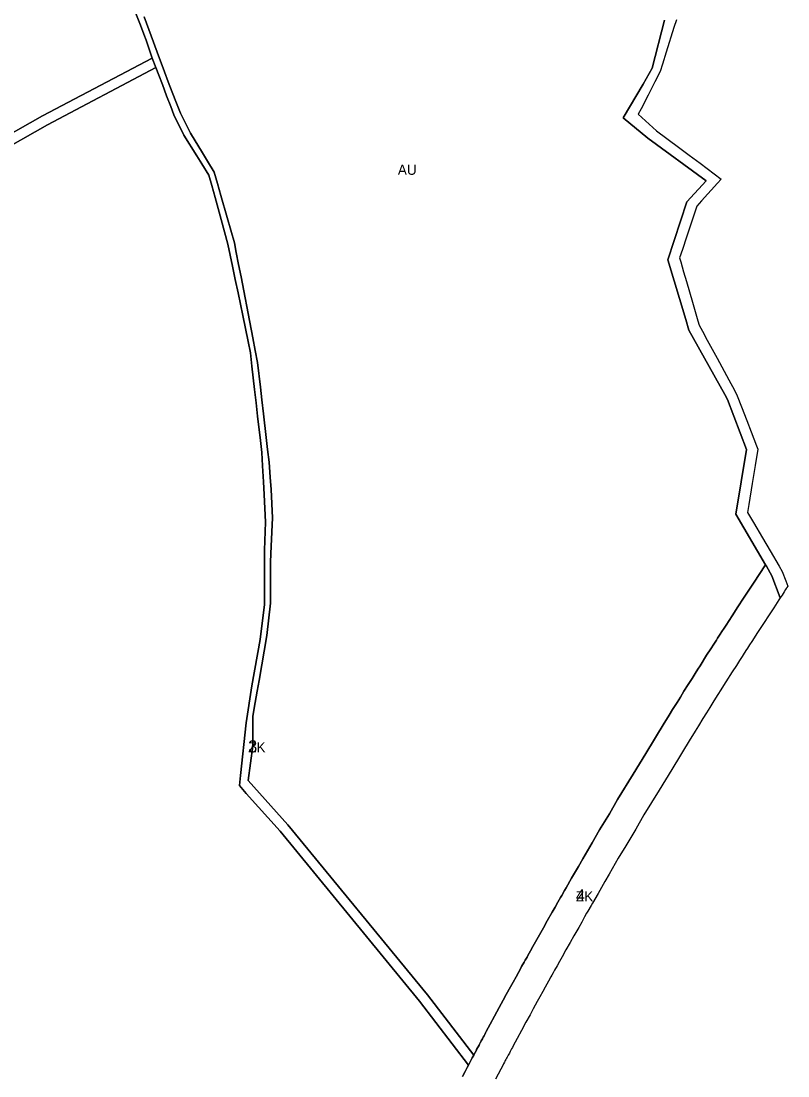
# Model space of a CAD drawing. Extents: x -537068 to -534056, y -1176840 to -1172401.
# Drawn here: x -536126 to -535749, y -1173679 to -1173160 of the extents above; entities that cross this region are included whole.
import ezdxf

# ---------------------------------------------------------------- set-up
doc = ezdxf.new("R2010")
doc.units = 0
for name, color, linetype in [('90710023', 7, 'Continuous'), ('90750013', 7, 'Continuous'), ('ID_navrh', 7, 'Continuous')]:
    doc.layers.add(name, color=color, linetype=linetype)

msp = doc.modelspace()

# ---------------------------------------------------------------- linework, layer by layer
at = {"layer": '90710023'}
for points in [[(-536065.55, -1173157.97), (-536062.1, -1173167.32), (-536059.13, -1173175.37), (-536055.51, -1173185.16), (-536053.65, -1173189.98), (-536051.66, -1173195.15), (-536049.6, -1173200.51), (-536047.69, -1173205.46), (-536042.77, -1173215.28), (-536036.86, -1173224.98), (-536034.34, -1173229.1), (-536031.04, -1173234.52), (-536029.45, -1173240.07), (-536027.76, -1173245.96), (-536024.67, -1173256.74), (-536021.09, -1173269.25), (-536020.15, -1173273.99), (-536018.99, -1173279.85), (-536017.77, -1173286), (-536016.39, -1173292.96), (-536014.27, -1173304.03), (-536011.97, -1173316.03), (-536010.78, -1173322.21), (-536009.63, -1173328.22), (-536008.28, -1173340.22), (-536007.57, -1173346.57), (-536006.8, -1173353.38), (-536005.48, -1173365.05), (-536004.73, -1173370.93), (-536003.93, -1173377.2), (-536003.43, -1173384.66), (-536003.02, -1173390.65), (-536002.3, -1173404.63), (-536002.99, -1173418.53), (-536003.38, -1173426.31), (-536003.35, -1173433.33), (-536003.3, -1173446.59), (-536005.11, -1173462.48), (-536008.94, -1173484.69), (-536009.84, -1173489.93), (-536010.81, -1173495.52), (-536011.97, -1173502.26), (-536012.07, -1173516.8), (-536014.28, -1173533.95), (-535994.71, -1173555.65), (-535926, -1173639.4), (-535903.28, -1173669.08), (-535904.02, -1173670.46), (-535905.86, -1173673.94), (-535929.92, -1173642.51), (-535998.5, -1173558.91), (-536015.29, -1173540.29), (-536018.62, -1173536.28), (-536018.08, -1173531.45), (-536015.31, -1173505.45), (-536012.55, -1173487.33), (-536008.37, -1173464.48), (-536006.32, -1173447.22), (-536006.32, -1173434.45), (-536006.31, -1173420.53), (-536005.72, -1173406.73), (-536006.38, -1173393.17), (-536006.76, -1173386.89), (-536007.24, -1173378.98), (-536007.64, -1173372.39), (-536008.3, -1173366.53), (-536009.65, -1173354.61), (-536010.39, -1173348.05), (-536011.14, -1173341.39), (-536012.43, -1173330.02), (-536013.18, -1173323.35), (-536014.34, -1173317.77), (-536016.98, -1173305.06), (-536019.31, -1173293.84), (-536020.65, -1173287.38), (-536022.03, -1173280.77), (-536023.15, -1173275.37), (-536024.29, -1173269.88), (-536027.6, -1173257.84), (-536030.57, -1173247.02), (-536032.22, -1173240.99), (-536033.6, -1173235.97), (-536037.11, -1173230.34), (-536039.56, -1173226.42), (-536045.93, -1173216.22), (-536050.86, -1173206.32), (-536052.44, -1173202.14), (-536054.44, -1173196.88), (-536056.52, -1173191.4), (-536058.32, -1173186.65), (-536059.71, -1173182.99), (-536061.49, -1173178.28), (-536064.6, -1173169.52), (-536065.68, -1173166.48), (-536067.25, -1173162.07), (-536069.87, -1173155.47)], [(-535803.45, -1173159.52), (-535804.66, -1173163.34), (-535808.48, -1173175.4), (-535810.33, -1173181.24), (-535811.49, -1173184.9), (-535814.13, -1173190.06), (-535817.43, -1173196.52), (-535820.87, -1173203.25), (-535822.27, -1173205.99), (-535813.3, -1173214.08), (-535802.36, -1173222.24), (-535797.19, -1173226.1), (-535791.83, -1173230.1), (-535781.43, -1173237.85), (-535783.31, -1173239.94), (-535791.08, -1173248.57), (-535793.43, -1173251.18), (-535794.57, -1173254.61), (-535798.54, -1173266.53), (-535800.51, -1173272.46), (-535801.9, -1173276.62), (-535801.34, -1173278.55), (-535799.91, -1173283.48), (-535798.52, -1173288.28), (-535795.57, -1173298.46), (-535792.93, -1173307.6), (-535792.31, -1173309.75), (-535790.69, -1173312.73), (-535788.33, -1173317.08), (-535783.48, -1173326.02), (-535777.69, -1173336.69), (-535774.9, -1173341.83), (-535773.51, -1173344.62), (-535771.43, -1173350.02), (-535768.86, -1173356.67), (-535766.68, -1173362.33), (-535764.02, -1173369.25), (-535763.42, -1173370.8), (-535764.71, -1173378.86), (-535766.14, -1173387.77), (-535767.79, -1173398.05), (-535768.43, -1173402.02), (-535765.58, -1173406.86), (-535761.14, -1173414.39), (-535757.31, -1173420.88), (-535752.87, -1173428.42), (-535751.35, -1173430.99), (-535749.58, -1173435.6), (-535748.57, -1173438.22), (-535749.05, -1173438.92), (-535749.18, -1173439.12), (-535749.4, -1173439.46), (-535749.69, -1173439.9), (-535750.38, -1173440.96), (-535751.46, -1173442.6), (-535752.34, -1173443.92), (-535756.52, -1173433.09), (-535759.12, -1173428.42), (-535759.55, -1173427.69), (-535774.26, -1173402.73), (-535768.96, -1173371.03), (-535778.38, -1173346.41), (-535779.58, -1173343.92), (-535797.43, -1173312.23), (-535798.87, -1173306.98), (-535807.63, -1173277.69), (-535798.31, -1173249.15), (-535788.85, -1173238.8), (-535817.5, -1173217.68), (-535829.73, -1173207.78), (-535819.85, -1173191.11), (-535815.41, -1173183.23), (-535809.4, -1173159.72)], [(-536141.23, -1173221.22), (-536115.5, -1173206.7), (-536061.49, -1173178.28), (-536059.71, -1173182.99), (-536113.11, -1173211.09), (-536138.71, -1173225.54)], [(-535908.86, -1173679.62), (-535907.55, -1173677.14), (-535906.46, -1173675.09), (-535905.86, -1173673.94), (-535904.02, -1173670.46), (-535903.28, -1173669.08), (-535903.17, -1173668.87), (-535901.95, -1173666.59), (-535901.85, -1173666.38), (-535900.65, -1173664.14), (-535900.43, -1173663.74), (-535900.25, -1173663.39), (-535900.07, -1173663.07), (-535899.92, -1173662.79), (-535899.7, -1173662.38), (-535899.55, -1173662.09), (-535898.96, -1173660.98), (-535898.55, -1173660.22), (-535898.18, -1173659.52), (-535897.82, -1173658.85), (-535897.4, -1173658.09), (-535897.06, -1173657.45), (-535895.11, -1173653.88), (-535893.03, -1173649.85), (-535890.69, -1173645.55), (-535888.68, -1173642), (-535887.23, -1173639.23), (-535885.13, -1173635.47), (-535883.83, -1173633.11), (-535882.43, -1173630.59), (-535881.19, -1173628.33), (-535880.38, -1173626.87), (-535879.66, -1173625.53), (-535878.39, -1173623.27), (-535877.92, -1173622.41), (-535877.28, -1173621.27), (-535877.01, -1173620.8), (-535876.65, -1173620.11), (-535875.3, -1173617.76), (-535874.16, -1173615.65), (-535872.87, -1173613.38), (-535870.94, -1173609.84), (-535868.92, -1173606.35), (-535867.06, -1173602.94), (-535864.58, -1173598.72), (-535863.19, -1173596.23), (-535861.81, -1173593.77), (-535860.6, -1173591.56), (-535859.92, -1173590.48), (-535858.52, -1173588.01), (-535857.79, -1173586.75), (-535855.05, -1173582), (-535851.73, -1173576.17), (-535849.58, -1173572.47), (-535845.01, -1173564.51), (-535841.25, -1173558.24), (-535836.45, -1173550.32), (-535832.4, -1173543.21), (-535824.81, -1173530.76), (-535818.58, -1173520.62), (-535809.53, -1173505.74), (-535808.34, -1173503.8), (-535807.01, -1173501.67), (-535805.35, -1173498.96), (-535803.13, -1173495.5), (-535801.49, -1173492.81), (-535799.75, -1173489.97), (-535797.64, -1173486.68), (-535795.75, -1173483.65), (-535794.22, -1173481.21), (-535792.89, -1173479.13), (-535791.81, -1173477.39), (-535788.58, -1173472.27), (-535786.52, -1173469.1), (-535785.09, -1173466.85), (-535783.78, -1173464.76), (-535783.18, -1173463.84), (-535781.92, -1173461.89), (-535781.08, -1173460.57), (-535780, -1173458.96), (-535779.02, -1173457.4), (-535776.09, -1173452.86), (-535773.22, -1173448.37), (-535770.39, -1173444.13), (-535768.15, -1173440.65), (-535765.55, -1173436.7), (-535759.55, -1173427.69), (-535759.12, -1173428.42), (-535756.52, -1173433.09), (-535752.34, -1173443.92), (-535753.05, -1173444.98), (-535755.58, -1173448.83), (-535757.85, -1173452.35), (-535760.66, -1173456.57), (-535763.47, -1173460.97), (-535766.37, -1173465.46), (-535767.41, -1173467.11), (-535768.51, -1173468.76), (-535769.29, -1173469.99), (-535770.58, -1173471.97), (-535771.12, -1173472.81), (-535772.4, -1173474.86), (-535773.9, -1173477.22), (-535775.95, -1173480.36), (-535779.1, -1173485.35), (-535780.2, -1173487.12), (-535781.54, -1173489.23), (-535783.04, -1173491.61), (-535784.97, -1173494.7), (-535787.04, -1173497.94), (-535788.7, -1173500.63), (-535790.41, -1173503.44), (-535792.64, -1173506.93), (-535794.26, -1173509.57), (-535795.59, -1173511.7), (-535796.72, -1173513.55), (-535805.78, -1173528.45), (-535812.02, -1173538.6), (-535819.48, -1173550.82), (-535823.51, -1173557.91), (-535828.4, -1173565.98), (-535832.07, -1173572.1), (-535836.59, -1173579.98), (-535838.73, -1173583.65), (-535842.03, -1173589.46), (-535844.79, -1173594.23), (-535845.5, -1173595.47), (-535847.04, -1173598.17), (-535847.65, -1173599.15), (-535848.69, -1173601.04), (-535850.1, -1173603.55), (-535851.56, -1173606.18), (-535854.01, -1173610.34), (-535855.84, -1173613.7), (-535857.86, -1173617.18), (-535859.76, -1173620.67), (-535861.04, -1173622.93), (-535862.2, -1173625.07), (-535863.5, -1173627.33), (-535863.82, -1173627.94), (-535864.19, -1173628.6), (-535864.82, -1173629.72), (-535865.29, -1173630.57), (-535866.5, -1173632.73), (-535867.21, -1173634.07), (-535868.07, -1173635.6), (-535869.29, -1173637.83), (-535870.7, -1173640.37), (-535872.01, -1173642.75), (-535874.03, -1173646.36), (-535875.5, -1173649.17), (-535877.58, -1173652.84), (-535879.78, -1173656.88), (-535881.86, -1173660.91), (-535883.86, -1173664.58), (-535884.21, -1173665.24), (-535884.64, -1173666.01), (-535884.96, -1173666.61), (-535885.31, -1173667.27), (-535885.72, -1173668.05), (-535886.31, -1173669.14), (-535886.46, -1173669.43), (-535886.68, -1173669.83), (-535886.84, -1173670.13), (-535887.04, -1173670.5), (-535887.21, -1173670.83), (-535887.43, -1173671.24), (-535887.71, -1173671.75), (-535887.91, -1173672.13), (-535888.16, -1173672.6), (-535888.55, -1173673.33), (-535888.56, -1173673.34), (-535888.56, -1173673.35), (-535888.57, -1173673.37), (-535888.58, -1173673.38), (-535888.58, -1173673.39), (-535888.58, -1173673.4), (-535888.59, -1173673.4), (-535888.59, -1173673.41), (-535888.6, -1173673.43), (-535888.61, -1173673.44), (-535888.62, -1173673.46), (-535889.92, -1173675.92), (-535891.24, -1173678.38), (-535892.54, -1173680.85)]]:
    msp.add_lwpolyline(points, dxfattribs=at)
at = {"layer": '90750013'}
for points in [[(-536069.87, -1173155.47), (-536067.25, -1173162.07), (-536065.68, -1173166.48), (-536064.6, -1173169.52), (-536061.49, -1173178.28), (-536115.5, -1173206.7), (-536141.23, -1173221.22)], [(-535809.4, -1173159.72), (-535815.41, -1173183.23), (-535819.85, -1173191.11), (-535829.73, -1173207.78), (-535817.5, -1173217.68), (-535788.85, -1173238.8), (-535798.31, -1173249.15), (-535807.63, -1173277.69), (-535798.87, -1173306.98), (-535797.43, -1173312.23), (-535779.58, -1173343.92), (-535778.38, -1173346.41), (-535768.96, -1173371.03), (-535774.26, -1173402.73), (-535759.55, -1173427.69), (-535765.55, -1173436.7), (-535768.15, -1173440.65), (-535770.39, -1173444.13), (-535773.22, -1173448.37), (-535776.09, -1173452.86), (-535779.02, -1173457.4), (-535780, -1173458.96), (-535781.08, -1173460.57), (-535781.92, -1173461.89), (-535783.18, -1173463.84), (-535783.78, -1173464.76), (-535785.09, -1173466.85), (-535786.52, -1173469.1), (-535788.58, -1173472.27), (-535791.81, -1173477.39), (-535792.89, -1173479.13), (-535794.22, -1173481.21), (-535795.75, -1173483.65), (-535797.64, -1173486.68), (-535799.75, -1173489.97), (-535801.49, -1173492.81), (-535803.13, -1173495.5), (-535805.35, -1173498.96), (-535807.01, -1173501.67), (-535808.34, -1173503.8), (-535809.53, -1173505.74), (-535818.58, -1173520.62), (-535824.81, -1173530.76), (-535832.4, -1173543.21), (-535836.45, -1173550.32), (-535841.25, -1173558.24), (-535845.01, -1173564.51), (-535849.58, -1173572.47), (-535851.73, -1173576.17), (-535855.05, -1173582), (-535857.79, -1173586.75), (-535858.52, -1173588.01), (-535859.92, -1173590.48), (-535860.6, -1173591.56), (-535861.81, -1173593.77), (-535863.19, -1173596.23), (-535864.58, -1173598.72), (-535867.06, -1173602.94), (-535868.92, -1173606.35), (-535870.94, -1173609.84), (-535872.87, -1173613.38), (-535874.16, -1173615.65), (-535875.3, -1173617.76), (-535876.65, -1173620.11), (-535877.01, -1173620.8), (-535877.28, -1173621.27), (-535877.92, -1173622.41), (-535878.39, -1173623.27), (-535879.66, -1173625.53), (-535880.38, -1173626.87), (-535881.19, -1173628.33), (-535882.43, -1173630.59), (-535883.83, -1173633.11), (-535885.13, -1173635.47), (-535887.23, -1173639.23), (-535888.68, -1173642), (-535890.69, -1173645.55), (-535893.03, -1173649.85), (-535895.11, -1173653.88), (-535897.06, -1173657.45), (-535897.4, -1173658.09), (-535897.82, -1173658.85), (-535898.18, -1173659.52), (-535898.55, -1173660.22), (-535898.96, -1173660.98), (-535899.55, -1173662.09), (-535899.7, -1173662.38), (-535899.92, -1173662.79), (-535900.07, -1173663.07), (-535900.25, -1173663.39), (-535900.43, -1173663.74), (-535900.65, -1173664.14), (-535901.85, -1173666.38), (-535901.95, -1173666.59), (-535903.17, -1173668.87), (-535903.28, -1173669.08), (-535926, -1173639.4), (-535994.71, -1173555.65), (-536014.28, -1173533.95), (-536012.07, -1173516.8), (-536011.97, -1173502.26), (-536010.81, -1173495.52), (-536009.84, -1173489.93), (-536008.94, -1173484.69), (-536005.11, -1173462.48), (-536003.3, -1173446.59), (-536003.35, -1173433.33), (-536003.38, -1173426.31), (-536002.99, -1173418.53), (-536002.3, -1173404.63), (-536003.02, -1173390.65), (-536003.43, -1173384.66), (-536003.93, -1173377.2), (-536004.73, -1173370.93), (-536005.48, -1173365.05), (-536006.8, -1173353.38), (-536007.57, -1173346.57), (-536008.28, -1173340.22), (-536009.63, -1173328.22), (-536010.78, -1173322.21), (-536011.97, -1173316.03), (-536014.27, -1173304.03), (-536016.39, -1173292.96), (-536017.77, -1173286), (-536018.99, -1173279.85), (-536020.15, -1173273.99), (-536021.09, -1173269.25), (-536024.67, -1173256.74), (-536027.76, -1173245.96), (-536029.45, -1173240.07), (-536031.04, -1173234.52), (-536034.34, -1173229.1), (-536036.86, -1173224.98), (-536042.77, -1173215.28), (-536047.69, -1173205.46), (-536049.6, -1173200.51), (-536051.66, -1173195.15), (-536053.65, -1173189.98), (-536055.51, -1173185.16), (-536059.13, -1173175.37), (-536062.1, -1173167.32), (-536065.55, -1173157.97)], [(-536138.71, -1173225.54), (-536113.11, -1173211.09), (-536059.71, -1173182.99), (-536058.32, -1173186.65), (-536056.52, -1173191.4), (-536054.44, -1173196.88), (-536052.44, -1173202.14), (-536050.86, -1173206.32), (-536045.93, -1173216.22), (-536039.56, -1173226.42), (-536037.11, -1173230.34), (-536033.6, -1173235.97), (-536032.22, -1173240.99), (-536030.57, -1173247.02), (-536027.6, -1173257.84), (-536024.29, -1173269.88), (-536023.15, -1173275.37), (-536022.03, -1173280.77), (-536020.65, -1173287.38), (-536019.31, -1173293.84), (-536016.98, -1173305.06), (-536014.34, -1173317.77), (-536013.18, -1173323.35), (-536012.43, -1173330.02), (-536011.14, -1173341.39), (-536010.39, -1173348.05), (-536009.65, -1173354.61), (-536008.3, -1173366.53), (-536007.64, -1173372.39), (-536007.24, -1173378.98), (-536006.76, -1173386.89), (-536006.38, -1173393.17), (-536005.72, -1173406.73), (-536006.31, -1173420.53), (-536006.32, -1173434.45), (-536006.32, -1173447.22), (-536008.37, -1173464.48), (-536012.55, -1173487.33), (-536015.31, -1173505.45), (-536018.08, -1173531.45), (-536018.62, -1173536.28), (-536015.29, -1173540.29), (-535998.5, -1173558.91), (-535929.92, -1173642.51), (-535905.86, -1173673.94), (-535906.46, -1173675.09), (-535907.55, -1173677.14), (-535908.86, -1173679.62)]]:
    msp.add_lwpolyline(points, dxfattribs=at)

# ---------------------------------------------------------------- texts
at = {"layer": '90710023'}
for p in [(-536014.29, -1173520.08), (-535852.95, -1173593.43)]:
    msp.add_text('ZK', height=5, rotation=360, dxfattribs=at).set_placement(p)
at = {"layer": '90750013'}
msp.add_text('AU', height=5, rotation=0, dxfattribs=at).set_placement((-535940.63, -1173235.78))
at = {"layer": 'ID_navrh'}
for s, p in [('3', (-536014.29, -1173520.08)), ('4', (-535852.95, -1173593.43))]:
    msp.add_text(s, height=6, rotation=360, dxfattribs=at).set_placement(p)

doc.saveas('drawing.dxf')
